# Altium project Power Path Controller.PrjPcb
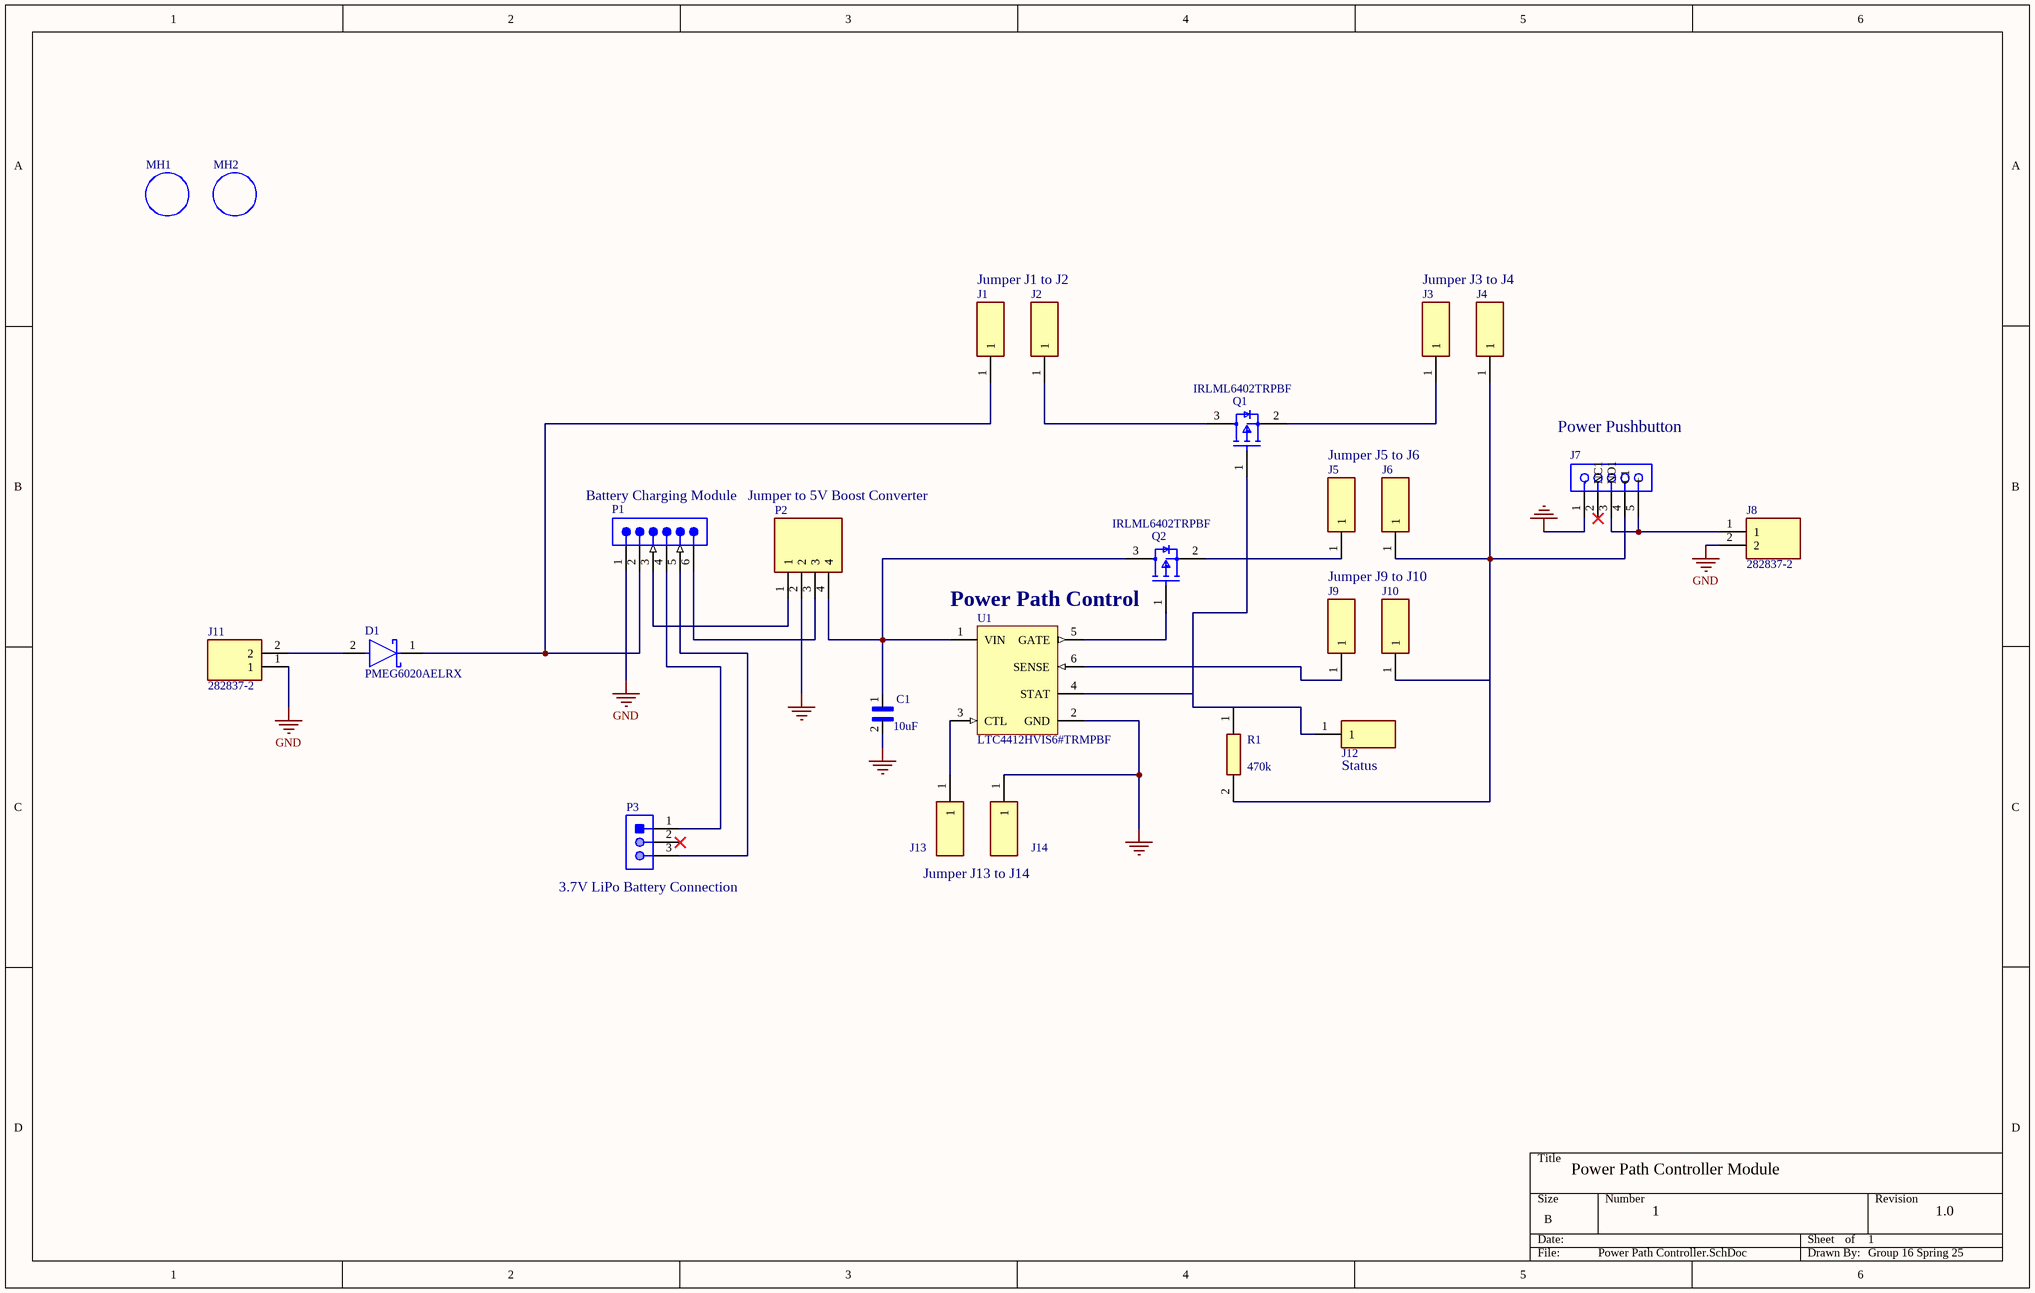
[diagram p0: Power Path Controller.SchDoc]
1 sheet, 25 parts. Net scope: global (net labels, ports and power ports of the same name join across sheets).
Board file: Power Path Controller.PcbDoc

## Sheet Power Path Controller.SchDoc
size B; SheetNumber: 1; SheetTotal: 1

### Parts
C1  10uF  [CAPRR254W50L508T317H508]
D1  PMEG6020AELRX  [FP-SOD123W-MFG]
J1  SSW-101-01-T-S  [SSW-101-XX-YYY-S]  (value not drawn)
J2  SSW-101-01-T-S  [SSW-101-XX-YYY-S]  (value not drawn)
J3  SSW-101-01-T-S  [SSW-101-XX-YYY-S]  (value not drawn)
J4  SSW-101-01-T-S  [SSW-101-XX-YYY-S]  (value not drawn)
J5  SSW-101-01-T-S  [SSW-101-XX-YYY-S]  (value not drawn)
J6  SSW-101-01-T-S  [SSW-101-XX-YYY-S]  (value not drawn)
J7  Power Pushbutton  [61300511821]
J8  282837-2  [2828372]
J9  SSW-101-01-T-S  [SSW-101-XX-YYY-S]  (value not drawn)
J10  SSW-101-01-T-S  [SSW-101-XX-YYY-S]  (value not drawn)
J11  282837-2  [2828372]
J12  Status  [SSW-101-XX-YYY-S]
J13  SSW-101-01-T-S  [SSW-101-XX-YYY-S]  (value not drawn)
J14  SSW-101-01-T-S  [SSW-101-XX-YYY-S]  (value not drawn)
MH1  Mounting Hole  [MTHNP3P2MM]  (value not drawn)
MH2  Mounting Hole  [MTHNP3P2MM]  (value not drawn)
P1  Battery Charging Module  [61300611121]
P2  Jumper to 5V Boost Converter  [HDRV4W40P127_1X4_508X214X400P]
P3  3.7V LiPo Battery Connection  [MOLX-530470310_V]
Q1  IRLML6402TRPBF  [FP-Micro3-MFG]
Q2  IRLML6402TRPBF  [FP-Micro3-MFG]
R1  470k  [RESAD1520W63L600D230]
U1  LTC4412HVIS6#TRMPBF  [LT-S6-6-TSOT-23_N]

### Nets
GND: C1.2 J7.1(-) J8.2 J11.1 J14.1 P1.1 P2.2 U1.2(GND)
NetC1_1: C1.1 P2.4 Q2.3(D) U1.1(VIN)
NetD1_1: D1.1(C) J1.1 P1.2
NetD1_2: D1.2(A) J11.2
NetJ2_1: J2.1 Q1.3(D)
NetJ3_1: J3.1 Q1.2(S)
NetJ4_1: J4.1 J6.1 J7.4(C1) J10.1 R1.2
NetJ5_1: J5.1 Q2.2(S)
NetJ7_3: J7.3(NO1) J7.5(+) J8.1
NetJ9_1: J9.1 U1.6(SENSE)
NetJ12_1: J12.1 Q1.1(G) R1.1 U1.4(STAT)
NetJ13_1: J13.1 U1.3(CTL)
NetP1_3: P1.3 P2.1
NetP1_4: P1.4 P3.1
NetP1_5: P1.5 P3.3
NetP1_6: P1.6 P2.3
NetQ2_1: Q2.1(G) U1.5(GATE)

Not connected (* = marked no-connect by the designer): J7 2(NC1)*; P3 2*

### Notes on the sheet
- Jumper J1 to J2
- Jumper J3 to J4
- Jumper J5 to J6
- (near P2) Module charging current is 1A. 3Ah capacity battery has standard charging of 0.6C (1.8A). Replace R3 (1.2k) with ~660 Ohm resistor or add a resistor in parallel to reduce the resistance to achieve 1.8A charging current. Equation: Icharge = 1200V /Rprogram from the TP4056 datasheet
- (near Q2) Power Path Control
- Jumper J9 to J10
- Jumper J13 to J14
- Power Path Controller Module
- 1
- 1.0
- Group 16 Spring 25

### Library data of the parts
C1 = FA16X7R1E106KRU00: 10 ÂµF Â±10% 25V Ceramic Capacitor X7R Radial; MF: TDK
D1 = CMP-14398-000040-1: DIODE SCHOTTKY 60V 2A CFP3
J1-J6 J9 J10 J13 J14 = SSW-101-01-T-S: Connector; Manufacturer_Name: SAMTEC
J7 = CMP-1502-01320-3: 61300511821; NexarPartId: 61924716; Current Rating: 3A; Operating Supply Voltage: 250V; Gender: Female; Contact Resistance: 20mΩ
J8 J11 = 282837-2: Connector; Manufacturer_Name: TE Connectivity
J12 = SSW-101-01-T-S: Connector SSW-101-01-T-S; Manufacturer_Name: SAMTEC
P1 = CMP-1502-01070-3: Dual Protection TP4056 (see pin tab for pin assignments); NexarPartId: 20084590; Current Rating: 3A; Pitch: 2.54mm; Gender: Male; Operating Supply Voltage: 250V; Connector Type: Male Pin; Number of Positions: 6; Contact Resistance: 20mΩ
P2 = 61300411821: Connector GRPB041VWVN-RC (needs to be changed to fit standard header pins); Manufacturer_Name: Wurth Elektronik
P3 = CMP-2000-05465-1: Male Header, Pitch 1.25 mm, 1 x 3 Position, Height 4.2 mm, Tail Length 2.3 mm, -40 to 85 degC, RoHS, Tray 530470310 (see pin tab for pin assignments); Manufacturer: Molex
Q1 Q2 = CMP-32901-000130-1: MOSFET P-CH 20V 3.7A SOT-23; Manufacturer: Infineon; Reverse Recovery Time: 29ns; Max Forward Diode Voltage: -1.2V; Input Capacitace At Vds: 633pF @ -10V; Drain To Source Resistance: 0.05Ω; Gate To Source Voltage: 12V; Max Junction Temp: +150°C; Pulse Drain Current: -22A; Threshold Vgs Min: -0.4V; Turn Off Delay Time: 588ns; Number Of Channels: 1; Power Dissipation: 1.3W; Turn On Delay Time: 350ns; Drain To Source Breakdown Voltage: -20V; Continuous Drain Current: -3.7A; Depletion Mode: False; Gate Charge At Vgs: 8nC @ -5V; Rthja Max: 75°C/W; Threshold Vgs: -0.55V; Standoff Height: 0.01mm; Reverse Recovery Charge: 11nC
R1 = CF14JT470K: Resistor CF14JT470K; Manufacturer_Name: Stackpole Electronics
U1 = CMP-0479-00434-1: Low Loss PowerPath(TM) Controller, 2.5 to 36 V Vin, 6-pin SOT23 (S6-6), -40 to 125 degC, Pb-Free, Mini Tape and Reel; Manufacturer: Linear Technology; Ideal Diode: Single, External, P-Channel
